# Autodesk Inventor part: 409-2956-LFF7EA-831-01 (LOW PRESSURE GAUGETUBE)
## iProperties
Created: 2010-09
Part Number: 409-2956-LFF7EA-831-01 (LOW PRESSURE GAUGETUBE)
Material: 3/8" OD TUBE - SS
Document SubType Name: Modeling
Designer: S. Boerckel
Engineer: Steve Boerckel
Mass: 61.6007 g
Surface Area: 127.01 cm^2
Volume: 7.62385 cm^3
Density: 8.08 g/cm^3
Description: LOWE PRESSURE GAUGE TUBE
Length: 13.797 in
Author: S. Boerckel
Revision Number: 0
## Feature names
1. Sweep3
